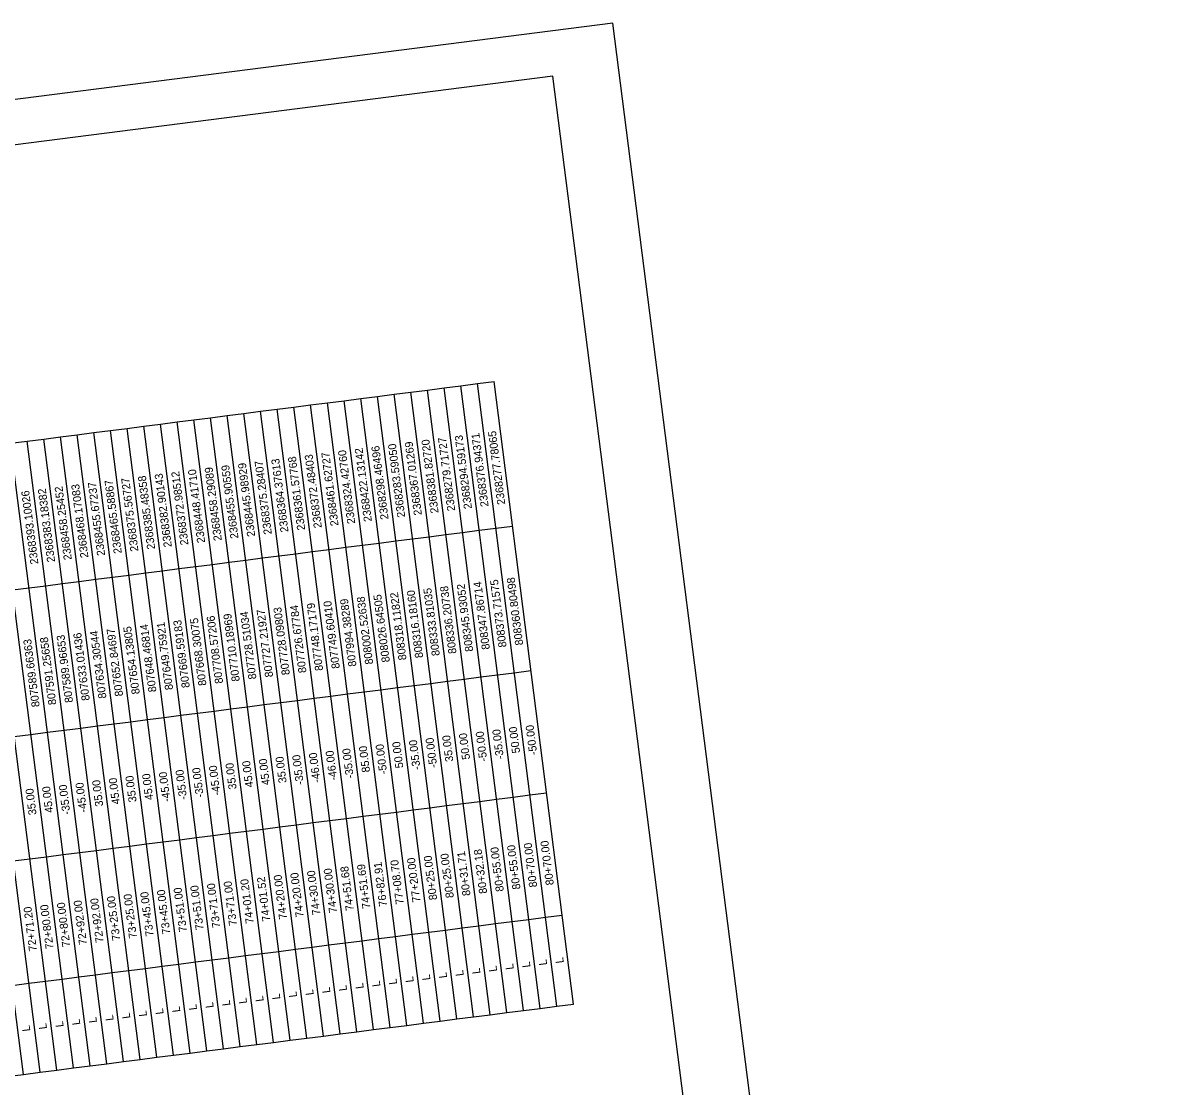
# Model space of a CAD drawing. Extents: x 2364621 to 2374814, y 792603 to 806745.
# Drawn here: x 2371409 to 2374814, y 803612 to 806745 of the extents above; entities that cross this region are included whole.
import ezdxf

# ---------------------------------------------------------------- set-up
doc = ezdxf.new("R2010")
doc.units = 0
for name, color, linetype in [('CTL Sheet Border CELL', 7, 'Continuous'), ('CTL Sheet Table Cell', 7, 'Continuous'), ('CTL Sheet Text', 7, 'Continuous'), ('Scratch_Level_0', 7, 'Continuous')]:
    doc.layers.add(name, color=color, linetype=linetype)

msp = doc.modelspace()

# ---------------------------------------------------------------- linework, layer by layer
at = {"layer": 'CTL Sheet Border CELL'}
msp.add_lwpolyline([(2364831.4, 805549.1), (2366316.3, 793922.1), (2374455.2, 794961.6), (2372970.2, 806588.6)], close=True, dxfattribs=at)
at = {"layer": 'CTL Sheet Table Cell'}
for p, q in [((2372551.3, 805658.1), (2372600.4, 805664.4)), ((2372600.4, 805664.4), (2372649.5, 805670.7)), ((2372834.6, 803830.7), (2372600.4, 805664.4)), ((2372649.5, 805670.7), (2372698.6, 805676.9)), ((2372883.7, 803836.9), (2372649.5, 805670.7)), ((2372698.6, 805676.9), (2372747.7, 805683.2)), ((2372932.8, 803843.2), (2372698.6, 805676.9)), ((2372747.7, 805683.2), (2372796.8, 805689.5)), ((2372981.9, 803849.5), (2372747.7, 805683.2)), ((2373031, 803855.7), (2372796.8, 805689.5)), ((2372305.7, 805626.7), (2372354.8, 805633)), ((2372354.8, 805633), (2372403.9, 805639.3)), ((2372589, 803799.3), (2372354.8, 805633)), ((2372403.9, 805639.3), (2372453, 805645.6)), ((2372638.1, 803805.6), (2372403.9, 805639.3)), ((2372453, 805645.6), (2372502.1, 805651.8)), ((2372687.2, 803811.8), (2372453, 805645.6)), ((2372502.1, 805651.8), (2372551.3, 805658.1)), ((2372736.3, 803818.1), (2372502.1, 805651.8)), ((2372785.5, 803824.4), (2372551.3, 805658.1)), ((2372011, 805589.1), (2372060.1, 805595.4)), ((2372060.1, 805595.4), (2372109.2, 805601.7)), ((2372294.3, 803761.6), (2372060.1, 805595.4)), ((2372109.2, 805601.7), (2372158.3, 805607.9)), ((2372343.4, 803767.9), (2372109.2, 805601.7)), ((2372158.3, 805607.9), (2372207.4, 805614.2)), ((2372392.5, 803774.2), (2372158.3, 805607.9)), ((2372207.4, 805614.2), (2372256.5, 805620.5)), ((2372441.6, 803780.5), (2372207.4, 805614.2)), ((2372256.5, 805620.5), (2372305.7, 805626.7)), ((2372490.7, 803786.7), (2372256.5, 805620.5)), ((2372539.9, 803793), (2372305.7, 805626.7)), ((2371765.4, 805557.7), (2371814.5, 805564)), ((2371814.5, 805564), (2371863.6, 805570.3)), ((2372048.7, 803730.3), (2371814.5, 805564)), ((2371863.6, 805570.3), (2371912.7, 805576.6)), ((2372097.8, 803736.6), (2371863.6, 805570.3)), ((2371912.7, 805576.6), (2371961.8, 805582.8)), ((2372146.9, 803742.8), (2371912.7, 805576.6)), ((2371961.8, 805582.8), (2372011, 805589.1)), ((2372196, 803749.1), (2371961.8, 805582.8)), ((2372245.2, 803755.4), (2372011, 805589.1)), ((2371519.8, 805526.4), (2371568.9, 805532.6)), ((2371568.9, 805532.6), (2371618, 805538.9)), ((2371803.1, 803698.9), (2371568.9, 805532.6)), ((2371618, 805538.9), (2371667.1, 805545.2)), ((2371852.2, 803705.2), (2371618, 805538.9)), ((2371667.1, 805545.2), (2371716.2, 805551.5)), ((2371901.3, 803711.5), (2371667.1, 805545.2)), ((2371716.2, 805551.5), (2371765.4, 805557.7)), ((2371950.5, 803717.7), (2371716.2, 805551.5)), ((2371999.6, 803724), (2371765.4, 805557.7)), ((2371508.4, 803661.3), (2371274.2, 805495)), ((2371557.5, 803667.5), (2371323.3, 805501.3)), ((2371372.4, 805507.6), (2371421.5, 805513.8)), ((2371606.6, 803673.8), (2371372.4, 805507.6)), ((2371421.5, 805513.8), (2371470.7, 805520.1)), ((2371655.7, 803680.1), (2371421.5, 805513.8)), ((2371470.7, 805520.1), (2371519.8, 805526.4)), ((2371704.9, 803686.4), (2371470.7, 805520.1)), ((2371754, 803692.6), (2371519.8, 805526.4)), ((2371410.2, 803648.7), (2371176, 805482.5)), ((2371459.3, 803655), (2371225.1, 805488.7)), ((2372753, 805251.2), (2372802.1, 805257.5)), ((2372802.1, 805257.5), (2372851.2, 805263.8)), ((2372507.4, 805219.9), (2372556.5, 805226.2)), ((2372556.5, 805226.2), (2372605.6, 805232.4)), ((2372605.6, 805232.4), (2372654.7, 805238.7)), ((2372654.7, 805238.7), (2372703.9, 805245)), ((2372703.9, 805245), (2372753, 805251.2)), ((2372212.7, 805182.2), (2372261.8, 805188.5)), ((2372261.8, 805188.5), (2372310.9, 805194.8)), ((2372310.9, 805194.8), (2372360, 805201.1)), ((2372360, 805201.1), (2372409.1, 805207.3)), ((2372409.1, 805207.3), (2372458.3, 805213.6)), ((2372458.3, 805213.6), (2372507.4, 805219.9)), ((2371967.1, 805150.9), (2372016.2, 805157.1)), ((2372016.2, 805157.1), (2372065.3, 805163.4)), ((2372065.3, 805163.4), (2372114.4, 805169.7)), ((2372114.4, 805169.7), (2372163.6, 805176)), ((2372163.6, 805176), (2372212.7, 805182.2)), ((2371672.4, 805113.2), (2371721.5, 805119.5)), ((2371721.5, 805119.5), (2371770.6, 805125.8)), ((2371770.6, 805125.8), (2371819.7, 805132.1)), ((2371819.7, 805132.1), (2371868.9, 805138.3)), ((2371868.9, 805138.3), (2371918, 805144.6)), ((2371918, 805144.6), (2371967.1, 805150.9)), ((2371426.8, 805081.9), (2371475.9, 805088.1)), ((2371475.9, 805088.1), (2371525, 805094.4)), ((2371525, 805094.4), (2371574.1, 805100.7)), ((2371574.1, 805100.7), (2371623.3, 805107)), ((2371623.3, 805107), (2371672.4, 805113.2)), ((2371377.7, 805075.6), (2371426.8, 805081.9)), ((2372660, 804806.7), (2372709.1, 804813)), ((2372709.1, 804813), (2372758.2, 804819.3)), ((2372758.2, 804819.3), (2372807.3, 804825.6)), ((2372807.3, 804825.6), (2372856.5, 804831.8)), ((2372856.5, 804831.8), (2372905.6, 804838.1)), ((2372414.4, 804775.4), (2372463.5, 804781.6)), ((2372463.5, 804781.6), (2372512.6, 804787.9)), ((2372512.6, 804787.9), (2372561.8, 804794.2)), ((2372561.8, 804794.2), (2372610.9, 804800.5)), ((2372610.9, 804800.5), (2372660, 804806.7)), ((2372168.8, 804744), (2372217.9, 804750.3)), ((2372217.9, 804750.3), (2372267, 804756.5)), ((2372267, 804756.5), (2372316.2, 804762.8)), ((2372316.2, 804762.8), (2372365.3, 804769.1)), ((2372365.3, 804769.1), (2372414.4, 804775.4)), ((2371874.1, 804706.4), (2371923.2, 804712.6)), ((2371923.2, 804712.6), (2371972.3, 804718.9)), ((2371972.3, 804718.9), (2372021.5, 804725.2)), ((2372021.5, 804725.2), (2372070.6, 804731.5)), ((2372070.6, 804731.5), (2372119.7, 804737.7)), ((2372119.7, 804737.7), (2372168.8, 804744)), ((2371628.5, 804675), (2371677.6, 804681.3)), ((2371677.6, 804681.3), (2371726.7, 804687.5)), ((2371726.7, 804687.5), (2371775.9, 804693.8)), ((2371775.9, 804693.8), (2371825, 804700.1)), ((2371825, 804700.1), (2371874.1, 804706.4)), ((2371382.9, 804643.6), (2371432, 804649.9)), ((2371432, 804649.9), (2371481.2, 804656.2)), ((2371481.2, 804656.2), (2371530.3, 804662.4)), ((2371530.3, 804662.4), (2371579.4, 804668.7)), ((2371579.4, 804668.7), (2371628.5, 804675)), ((2372902.5, 804471.6), (2372951.6, 804477.9)), ((2372607.8, 804434), (2372656.9, 804440.3)), ((2372656.9, 804440.3), (2372706, 804446.5)), ((2372706, 804446.5), (2372755.1, 804452.8)), ((2372755.1, 804452.8), (2372804.2, 804459.1)), ((2372804.2, 804459.1), (2372853.3, 804465.4)), ((2372853.3, 804465.4), (2372902.5, 804471.6)), ((2372362.2, 804402.6), (2372411.3, 804408.9)), ((2372411.3, 804408.9), (2372460.4, 804415.2)), ((2372460.4, 804415.2), (2372509.5, 804421.4)), ((2372509.5, 804421.4), (2372558.6, 804427.7)), ((2372558.6, 804427.7), (2372607.8, 804434)), ((2372067.5, 804365), (2372116.6, 804371.3)), ((2372116.6, 804371.3), (2372165.7, 804377.5)), ((2372165.7, 804377.5), (2372214.8, 804383.8)), ((2372214.8, 804383.8), (2372263.9, 804390.1)), ((2372263.9, 804390.1), (2372313, 804396.4)), ((2372313, 804396.4), (2372362.2, 804402.6)), ((2371821.9, 804333.6), (2371871, 804339.9)), ((2371871, 804339.9), (2371920.1, 804346.2)), ((2371920.1, 804346.2), (2371969.2, 804352.4)), ((2371969.2, 804352.4), (2372018.3, 804358.7)), ((2372018.3, 804358.7), (2372067.5, 804365)), ((2371527.2, 804296), (2371576.3, 804302.3)), ((2371576.3, 804302.3), (2371625.4, 804308.5)), ((2371625.4, 804308.5), (2371674.5, 804314.8)), ((2371674.5, 804314.8), (2371723.6, 804321.1)), ((2371723.6, 804321.1), (2371772.8, 804327.3)), ((2371772.8, 804327.3), (2371821.9, 804333.6)), ((2371379.8, 804277.2), (2371428.9, 804283.4)), ((2371428.9, 804283.4), (2371478, 804289.7)), ((2371478, 804289.7), (2371527.2, 804296)), ((2372801.1, 804092.6), (2372850.2, 804098.9)), ((2372850.2, 804098.9), (2372899.4, 804105.2)), ((2372899.4, 804105.2), (2372948.5, 804111.4)), ((2372948.5, 804111.4), (2372997.6, 804117.7)), ((2372555.5, 804061.2), (2372604.6, 804067.5)), ((2372604.6, 804067.5), (2372653.8, 804073.8)), ((2372653.8, 804073.8), (2372702.9, 804080.1)), ((2372702.9, 804080.1), (2372752, 804086.3)), ((2372752, 804086.3), (2372801.1, 804092.6)), ((2372260.8, 804023.6), (2372309.9, 804029.9)), ((2372309.9, 804029.9), (2372359.1, 804036.2)), ((2372359.1, 804036.2), (2372408.2, 804042.4)), ((2372408.2, 804042.4), (2372457.3, 804048.7)), ((2372457.3, 804048.7), (2372506.4, 804055)), ((2372506.4, 804055), (2372555.5, 804061.2)), ((2372015.2, 803992.2), (2372064.3, 803998.5)), ((2372064.3, 803998.5), (2372113.5, 804004.8)), ((2372113.5, 804004.8), (2372162.6, 804011.1)), ((2372162.6, 804011.1), (2372211.7, 804017.3)), ((2372211.7, 804017.3), (2372260.8, 804023.6)), ((2371769.6, 803960.9), (2371818.8, 803967.1)), ((2371818.8, 803967.1), (2371867.9, 803973.4)), ((2371867.9, 803973.4), (2371917, 803979.7)), ((2371917, 803979.7), (2371966.1, 803986)), ((2371966.1, 803986), (2372015.2, 803992.2)), ((2371474.9, 803923.2), (2371524, 803929.5)), ((2371524, 803929.5), (2371573.2, 803935.8)), ((2371573.2, 803935.8), (2371622.3, 803942.1)), ((2371622.3, 803942.1), (2371671.4, 803948.3)), ((2371671.4, 803948.3), (2371720.5, 803954.6)), ((2371720.5, 803954.6), (2371769.6, 803960.9)), ((2371376.7, 803910.7), (2371425.8, 803917)), ((2371425.8, 803917), (2371474.9, 803923.2)), ((2372785.5, 803824.4), (2372834.6, 803830.7)), ((2372834.6, 803830.7), (2372883.7, 803836.9)), ((2372883.7, 803836.9), (2372932.8, 803843.2)), ((2372932.8, 803843.2), (2372981.9, 803849.5)), ((2372981.9, 803849.5), (2373031, 803855.7)), ((2372490.7, 803786.7), (2372539.9, 803793)), ((2372539.9, 803793), (2372589, 803799.3)), ((2372589, 803799.3), (2372638.1, 803805.6)), ((2372638.1, 803805.6), (2372687.2, 803811.8)), ((2372687.2, 803811.8), (2372736.3, 803818.1)), ((2372736.3, 803818.1), (2372785.5, 803824.4)), ((2372245.2, 803755.4), (2372294.3, 803761.6)), ((2372294.3, 803761.6), (2372343.4, 803767.9)), ((2372343.4, 803767.9), (2372392.5, 803774.2)), ((2372392.5, 803774.2), (2372441.6, 803780.5)), ((2372441.6, 803780.5), (2372490.7, 803786.7)), ((2371950.5, 803717.7), (2371999.6, 803724)), ((2371999.6, 803724), (2372048.7, 803730.3)), ((2372048.7, 803730.3), (2372097.8, 803736.6)), ((2372097.8, 803736.6), (2372146.9, 803742.8)), ((2372146.9, 803742.8), (2372196, 803749.1)), ((2372196, 803749.1), (2372245.2, 803755.4)), ((2371704.9, 803686.4), (2371754, 803692.6)), ((2371754, 803692.6), (2371803.1, 803698.9)), ((2371803.1, 803698.9), (2371852.2, 803705.2)), ((2371852.2, 803705.2), (2371901.3, 803711.5)), ((2371901.3, 803711.5), (2371950.5, 803717.7)), ((2371410.2, 803648.7), (2371459.3, 803655)), ((2371459.3, 803655), (2371508.4, 803661.3)), ((2371508.4, 803661.3), (2371557.5, 803667.5)), ((2371557.5, 803667.5), (2371606.6, 803673.8)), ((2371606.6, 803673.8), (2371655.7, 803680.1)), ((2371655.7, 803680.1), (2371704.9, 803686.4)), ((2371361, 803642.5), (2371410.2, 803648.7))]:
    msp.add_line(p, q, dxfattribs=at)
at = {"layer": 'Scratch_Level_0'}
msp.add_lwpolyline([(2374814.3, 793692), (2373147.1, 806745.2), (2364620.8, 805656.2), (2366287.9, 792603)], close=True, dxfattribs=at)

# ---------------------------------------------------------------- texts
at = {"layer": 'CTL Sheet Text'}
for s, height, p in [('2368294.59173', 23.579, (2372731.7, 805315.5)), ('2368376.94371', 23.579, (2372780.8, 805321.8)), ('2368277.78065', 23.579, (2372829.9, 805328)), ('2368422.13142', 23.579, (2372437, 805277.8)), ('2368298.46496', 23.579, (2372486.1, 805284.1)), ('2368283.59050', 23.579, (2372535.2, 805290.4)), ('2368367.01269', 23.579, (2372584.3, 805296.7)), ('2368381.82720', 23.579, (2372633.5, 805302.9)), ('2368279.71727', 23.579, (2372682.6, 805309.2)), ('2368364.37613', 23.579, (2372191.4, 805246.5)), ('2368361.57768', 23.579, (2372240.5, 805252.7)), ('2368372.48403', 23.579, (2372289.6, 805259)), ('2368461.62727', 23.579, (2372338.8, 805265.3)), ('2368324.42760', 23.579, (2372387.9, 805271.6)), ('2368448.41710', 23.579, (2371945.8, 805215.1)), ('2368458.29089', 23.579, (2371994.9, 805221.4)), ('2368455.90559', 23.579, (2372044, 805227.7)), ('2368445.98929', 23.579, (2372093.2, 805233.9)), ('2368375.28407', 23.579, (2372142.3, 805240.2)), ('2368465.58867', 23.579, (2371700.2, 805183.7)), ('2368375.56727', 23.579, (2371749.3, 805190)), ('2368385.48358', 23.579, (2371798.5, 805196.3)), ('2368382.90143', 23.579, (2371847.6, 805202.6)), ('2368372.98512', 23.579, (2371896.7, 805208.8)), ('2368393.10026', 23.579, (2371454.6, 805152.4)), ('2368383.18382', 23.579, (2371503.7, 805158.6)), ('2368458.25452', 23.579, (2371552.9, 805164.9)), ('2368468.17083', 23.579, (2371602, 805171.2)), ('2368455.67237', 23.579, (2371651.1, 805177.5)), ('808336.20738', 23.579, (2372686.3, 804888.8)), ('808345.93052', 23.579, (2372735.5, 804895.1)), ('808347.86714', 23.579, (2372784.6, 804901.4)), ('808373.71575', 23.579, (2372833.7, 804907.7)), ('808360.80498', 23.579, (2372882.8, 804913.9)), ('808002.52638', 23.579, (2372440.8, 804857.5)), ('808026.64505', 23.579, (2372489.9, 804863.8)), ('808318.11822', 23.579, (2372539, 804870)), ('808316.18160', 23.579, (2372588.1, 804876.3)), ('808333.81035', 23.579, (2372637.2, 804882.6)), ('807728.09803', 23.579, (2372195.2, 804826.1)), ('807726.67784', 23.579, (2372244.3, 804832.4)), ('807748.17179', 23.579, (2372293.4, 804838.7)), ('807749.60410', 23.579, (2372342.5, 804844.9)), ('807994.38289', 23.579, (2372391.6, 804851.2)), ('807669.59183', 23.579, (2371900.5, 804788.5)), ('807668.30075', 23.579, (2371949.6, 804794.7)), ('807708.57206', 23.579, (2371998.7, 804801)), ('807710.18969', 23.579, (2372047.8, 804807.3)), ('807728.51034', 23.579, (2372096.9, 804813.6)), ('807727.21927', 23.579, (2372146, 804819.8)), ('807633.01436', 23.579, (2371605.8, 804750.8)), ('807634.30544', 23.579, (2371654.9, 804757.1)), ('807652.84697', 23.579, (2371704, 804763.4)), ('807654.13805', 23.579, (2371753.1, 804769.7)), ('807648.46814', 23.579, (2371802.2, 804775.9)), ('807649.75921', 23.579, (2371851.3, 804782.2)), ('807589.66363', 23.579, (2371458.4, 804732)), ('807591.25658', 23.579, (2371507.5, 804738.3)), ('807589.96653', 23.579, (2371556.6, 804744.6)), ('-50.00', 23.58, (2372924.1, 804590.6)), ('35.00', 23.58, (2372677, 804570.8)), ('50.00', 23.58, (2372726.2, 804577.1)), ('-50.00', 23.58, (2372776.8, 804571.8)), ('-35.00', 23.58, (2372825.9, 804578.1)), ('50.00', 23.58, (2372873.5, 804595.9)), ('-35.00', 23.58, (2372383.8, 804521.6)), ('85.00', 23.58, (2372431.5, 804539.5)), ('-50.00', 23.58, (2372482.1, 804534.2)), ('50.00', 23.58, (2372529.7, 804552)), ('-35.00', 23.58, (2372580.3, 804546.7)), ('-50.00', 23.58, (2372629.4, 804553)), ('45.00', 23.58, (2372136.7, 804501.8)), ('35.00', 23.58, (2372185.9, 804508.1)), ('-35.00', 23.58, (2372236.5, 804502.8)), ('-46.00', 23.58, (2372285.6, 804509.1)), ('-46.00', 23.58, (2372334.7, 804515.3)), ('-35.00', 23.58, (2371892.6, 804458.9)), ('-35.00', 23.58, (2371941.8, 804465.1)), ('-45.00', 23.58, (2371990.9, 804471.4)), ('35.00', 23.58, (2372038.5, 804489.3)), ('45.00', 23.58, (2372087.6, 804495.6)), ('-45.00', 23.58, (2371597.9, 804421.2)), ('35.00', 23.58, (2371645.6, 804439.1)), ('45.00', 23.58, (2371694.7, 804445.4)), ('35.00', 23.58, (2371743.8, 804451.7)), ('45.00', 23.58, (2371792.9, 804457.9)), ('-45.00', 23.58, (2371843.5, 804452.6)), ('35.00', 23.58, (2371449.1, 804414)), ('45.00', 23.58, (2371498.2, 804420.3)), ('-35.00', 23.58, (2371548.8, 804415)), ('80+70.00', 23.58, (2372973.1, 804207.2)), ('80+31.71', 23.58, (2372727.5, 804175.8)), ('80+32.18', 23.58, (2372776.6, 804182.1)), ('80+55.00', 23.58, (2372825.7, 804188.4)), ('80+55.00', 23.58, (2372874.8, 804194.7)), ('80+70.00', 23.58, (2372924, 804200.9)), ('76+82.91', 23.58, (2372481.9, 804144.5)), ('77+08.70', 23.58, (2372531, 804150.7)), ('77+20.00', 23.58, (2372580.1, 804157)), ('80+25.00', 23.58, (2372629.3, 804163.3)), ('80+25.00', 23.58, (2372678.4, 804169.6)), ('74+20.00', 23.58, (2372187.2, 804106.8)), ('74+20.00', 23.58, (2372236.3, 804113.1)), ('74+30.00', 23.58, (2372285.4, 804119.4)), ('74+30.00', 23.58, (2372334.5, 804125.7)), ('74+51.68', 23.58, (2372383.7, 804131.9)), ('74+51.69', 23.58, (2372432.8, 804138.2)), ('73+51.00', 23.58, (2371941.6, 804075.5)), ('73+71.00', 23.58, (2371990.7, 804081.7)), ('73+71.00', 23.58, (2372039.8, 804088)), ('74+01.20', 23.58, (2372089, 804094.3)), ('74+01.52', 23.58, (2372138.1, 804100.6)), ('72+92.00', 23.58, (2371646.9, 804037.8)), ('73+25.00', 23.58, (2371696, 804044.1)), ('73+25.00', 23.58, (2371745.1, 804050.4)), ('73+45.00', 23.58, (2371794.3, 804056.6)), ('73+45.00', 23.58, (2371843.4, 804062.9)), ('73+51.00', 23.58, (2371892.5, 804069.2)), ('72+71.20', 23.58, (2371450.4, 804012.7)), ('72+80.00', 23.58, (2371499.5, 804019)), ('72+80.00', 23.58, (2371548.7, 804025.3)), ('72+92.00', 23.58, (2371597.8, 804031.6)), ('L', 23.6, (2372756.8, 803946)), ('L', 23.6, (2372806, 803952.3)), ('L', 23.6, (2372855.1, 803958.5)), ('L', 23.6, (2372904.2, 803964.8)), ('L', 23.6, (2372953.3, 803971.1)), ('L', 23.6, (2373002.4, 803977.3)), ('L', 23.6, (2372511.3, 803914.6)), ('L', 23.6, (2372560.4, 803920.9)), ('L', 23.6, (2372609.5, 803927.2)), ('L', 23.6, (2372658.6, 803933.4)), ('L', 23.6, (2372707.7, 803939.7)), ('L', 23.6, (2372216.6, 803877)), ('L', 23.6, (2372265.7, 803883.2)), ('L', 23.6, (2372314.8, 803889.5)), ('L', 23.6, (2372363.9, 803895.8)), ('L', 23.6, (2372413, 803902.1)), ('L', 23.6, (2372462.1, 803908.3)), ('L', 23.6, (2371971, 803845.6)), ('L', 23.6, (2372020.1, 803851.9)), ('L', 23.6, (2372069.2, 803858.2)), ('L', 23.6, (2372118.3, 803864.4)), ('L', 23.6, (2372167.4, 803870.7)), ('L', 23.6, (2371725.4, 803814.2)), ('L', 23.6, (2371774.5, 803820.5)), ('L', 23.6, (2371823.6, 803826.8)), ('L', 23.6, (2371872.7, 803833.1)), ('L', 23.6, (2371921.8, 803839.3)), ('L', 23.6, (2371430.7, 803776.6)), ('L', 23.6, (2371479.8, 803782.9)), ('L', 23.6, (2371528.9, 803789.1)), ('L', 23.6, (2371578, 803795.4)), ('L', 23.6, (2371627.1, 803801.7)), ('L', 23.6, (2371676.3, 803808))]:
    msp.add_text(s, height=height, rotation=97.2784, dxfattribs=at).set_placement(p)

doc.saveas('drawing.dxf')
